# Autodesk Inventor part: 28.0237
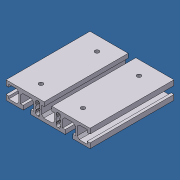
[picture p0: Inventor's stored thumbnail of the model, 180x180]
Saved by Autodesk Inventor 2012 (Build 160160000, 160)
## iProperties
Created: 2007-06
Part Number: 28.0237
Material: Aluminum-6061
Document SubType Name: Modeling
Designer: Andy Moles
Density: 2.71 g/cm^3
Description: L = 3.543", MACHINE TO 28.0237
Mass: 176.751 g
Surface Area: 445.108 cm^2
Volume: 65.2218 cm^3
Stock Number: 20.0995 PROFILE 90X19
Vendor: F
Author: Andy Moles
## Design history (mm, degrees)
sketch "Sketch1"
  geometry: L1 (18.4, -9.5)-(18.4, -5) reference; L2 (17.9, -5)-(15.7, -5) reference; L3 (15.7, -5)-(15.7, 3.5) reference; L4 (15.7, 3.5)-(18, 5.8) reference; L5 (18, 5.8)-(27, 5.8) reference; L6 (27, 5.8)-(29.3, 3.5) reference; L7 (29.3, 3.5)-(29.3, -5) reference; L8 (26.6, -5)-(26.6, -9.5) reference; L9 (45, -9.5)-(26.9, -9.5) reference; L10 (45, -4.1)-(45, -9.5) reference; L11 (45, -4.1)-(42, -4.1) reference; L12 (42, -4.6)-(42, -6.8) reference; L13 (42, -6.8)-(33.5, -6.8) reference; L14 (33.5, -6.8)-(31.2, -4.5) reference; L15 (31.2, -4.5)-(31.2, 4.5) reference; L16 (31.2, 4.5)-(33.5, 6.8) reference; L17 (33.5, 6.8)-(42, 6.8) reference; L18 (42, 4.1)-(45, 4.1) reference; L19 (45, 9.5)-(45, 4.1) reference; L20 (4.4, 9.5)-(45, 9.5) reference; L21 (4.1, 9.5)-(4.1, 5) reference; L22 (4.6, 5)-(6.8, 5) reference; L23 (6.8, 5)-(6.8, -3.5) reference; L24 (6.8, -3.5)-(4.5, -5.8) reference; L25 (4.5, -5.8)-(-4.5, -5.8) reference; L26 (-4.5, -5.8)-(-6.8, -3.5) reference; L27 (-6.8, -3.5)-(-6.8, 5) reference; L28 (-4.1, 5)-(-4.1, 9.5) reference; L29 (-45, 4.1)-(-45, 9.5) reference; L30 (-45, 4.1)-(-42, 4.1) reference; L31 (-42, 4.1)-(-42, 6.8) reference; L32 (-42, 6.8)-(-33.5, 6.8) reference; L33 (-33.5, 6.8)-(-31.2, 4.5) reference; L34 (-31.2, 4.5)-(-31.2, -4.5) reference; L35 (-31.2, -4.5)-(-33.5, -6.8) reference; L36 (-33.5, -6.8)-(-42, -6.8) reference; L37 (-42, -6.8)-(-42, -4.1) reference; L38 (-42, -4.1)-(-45, -4.1) reference; L39 (-45, -9.5)-(-45, -4.1) reference; L40 (-26.6, -9.5)-(-26.6, -5) reference; L41 (-29.3, -5)-(-29.3, 3.5) reference; L42 (-29.3, 3.5)-(-27, 5.8) reference; L43 (-27, 5.8)-(-18, 5.8) reference; L44 (-18, 5.8)-(-15.7, 3.5) reference; L45 (-15.7, 3.5)-(-15.7, -5) reference; L46 (-15.7, -5)-(-17.9, -5) reference; L47 (-18.4, -5)-(-18.4, -9.5) reference; L48 (-18.1, -9.5)-(-18.4, -9.5) reference; L49 (-26.6, -9.5)-(-45, -9.5) reference; L50 (-17.9, -5)-(-18.4, -5) reference; L51 (-26.6, -5)-(-29.3, -5) reference; L52 (-6.8, 5)-(-4.1, 5) reference; L53 (4.1, 5)-(4.6, 5) reference; L54 (-45, 9.5)-(-4.1, 9.5) reference; L55 (4.1, 9.5)-(4.4, 9.5) reference; L56 (29.3, -5)-(26.6, -5) reference; L57 (18.4, -5)-(17.9, -5) reference; L58 (26.9, -9.5)-(26.6, -9.5) reference; L59 (18.4, -9.5)-(-18.1, -9.5) reference; L60 (42, 6.8)-(42, 4.1) reference; L61 (42, -4.1)-(42, -4.6) reference; L62 (-9.354, -2.59)-(-8.993, -2.95); L63 (-10.7, -7)-(-11.3, -7); L64 (-8.7, -3.657)-(-8.7, -5)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; A1 r 2.5 centre (-11, 0) between (-9.333, -1.863) and (-9.333, 1.863); A2 r 1 centre (-9.7, -3.657) between (-8.7, -3.657) and (-8.993, -2.95); A3 r 2 centre (-10.7, -5) between (-10.7, -7) and (-8.7, -5); A4 r 0.5 centre (-9, -2.236) between (-9.333, -1.863) and (-9.354, -2.59); A5 r 1 centre (-12.3, -3.657) between (-13.007, -2.95) and (-13.3, -3.657); A6 r 2.5 centre (-11, 0) between (-12.667, 1.863) and (-12.667, -1.863); A7 r 2 centre (-11.3, -5) between (-13.3, -5) and (-11.3, -7); A8 r 0.5 centre (-13, -2.236) between (-12.646, -2.59) and (-12.667, -1.863); A9 r 0.5 centre (-13, 2.236) between (-12.667, 1.863) and (-12.646, 2.59); A10 r 2 centre (-11.3, 5) between (-11.3, 7) and (-13.3, 5); A11 r 0.5 centre (-9, 2.236) between (-9.354, 2.59) and (-9.333, 1.863); A12 r 1 centre (-9.7, 3.657) between (-8.993, 2.95) and (-8.7, 3.657); A13 r 2 centre (-10.7, 5) between (-8.7, 5) and (-10.7, 7); A14 r 1 centre (-12.3, 3.657) between (-13.3, 3.657) and (-13.007, 2.95); A15 r 1 centre (12.3, 3.657) between (13.007, 2.95) and (13.3, 3.657); A16 r 0.5 centre (13, 2.236) between (12.646, 2.59) and (12.667, 1.863); A17 r 2 centre (11.3, 5) between (13.3, 5) and (11.3, 7); A18 r 0.5 centre (9, 2.236) between (9.333, 1.863) and (9.354, 2.59); A19 r 1 centre (9.7, 3.657) between (8.7, 3.657) and (8.993, 2.95); A20 r 2 centre (10.7, 5) between (10.7, 7) and (8.7, 5); A21 r 1 centre (9.7, -3.657) between (8.993, -2.95) and (8.7, -3.657); A22 r 2.5 centre (11, 0) between (9.333, 1.863) and (9.333, -1.863); A23 r 0.5 centre (9, -2.236) between (9.354, -2.59) and (9.333, -1.863); A24 r 2 centre (10.7, -5) between (8.7, -5) and (10.7, -7); A25 r 2.5 centre (11, 0) between (12.667, -1.863) and (12.667, 1.863); A26 r 0.5 centre (13, -2.236) between (12.667, -1.863) and (12.646, -2.59); A27 r 1 centre (12.3, -3.657) between (13.3, -3.657) and (13.007, -2.95); A28 r 2 centre (11.3, -5) between (11.3, -7) and (13.3, -5)
  constraints: 162 end point, 56 point on circle, 28 centre point, 28 horizontal, 23 vertical, 71 other
extrude "Extrusion1" new body sketch "Sketch1" stored distance "d0" = 90; taper "d1" = 0 deg
sketch "Sketch2"
  geometry: L1 (-26.6, -90)-(-26.6, 0) reference; L2 (63.4, -90)-(63.4, 0) reference; L3 (-8.2, 0)-(-26.6, 0) reference; L4 (-26.6, -90)-(-8.2, -90) reference; 5 further points
  constraints: 2 horizontal alignment, 2 vertical alignment
  dimensions: "d2" = 22.5 distance from line of point (-4.1, -15) L1; "d3" = 22.5 distance from line of point (40.9, -15) L2; "d4" = 15 distance from line of point (-4.1, -15) L3; "d5" = 15 distance from line of point (-4.1, -75) L4
hole "Hole1" sketch "Sketch2" at (40.9, -15), (40.9, -75), (-4.1, -75), (-4.1, -15) diameter "d6" = 4.5; stored, may be unused: countersink angle "d10" = 90 deg, drill point angle "d12" = 118 deg; dims "d7" = 6, "d8" = 4, "d9" = 2, "d11" = 4.5
body "Solid1"
